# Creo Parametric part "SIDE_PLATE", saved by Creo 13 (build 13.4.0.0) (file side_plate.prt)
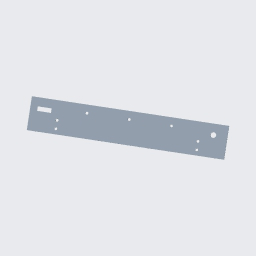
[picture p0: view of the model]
Units: millimeter Newton Second (mmNs); MM, TONNE, SECS

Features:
  1. datum plane "RIGHT"
  2. datum plane "TOP"
  3. datum plane "FRONT"
  4. coordinate system
  5. protrusion
  6. cut
  7. datum axis

Surfaces: 10 plane, 8 cylinder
